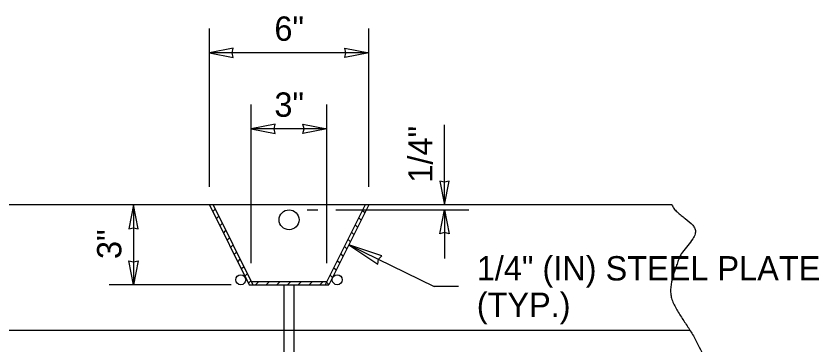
# Model space of a CAD drawing. Extents: x 99862 to 103151, y 100000 to 117076.
# Drawn here: x 101760 to 102289, y 109980 to 110196 of the extents above; entities that cross this region are included whole.
import ezdxf

# ---------------------------------------------------------------- set-up
doc = ezdxf.new("R2010")
doc.units = 0
for name, color, linetype in [('Level 10', 7, 'Continuous'), ('Level 11', 7, 'Continuous'), ('Level 14', 7, 'Continuous'), ('Level 15', 7, 'Continuous'), ('Level 16', 7, 'Continuous'), ('Level 20', 7, 'Continuous'), ('Level 30', 7, 'Continuous'), ('Level 40', 7, 'Continuous')]:
    doc.layers.add(name, color=color, linetype=linetype)

msp = doc.modelspace()

# ---------------------------------------------------------------- linework, layer by layer
at = {"layer": 'Level 10'}
for centre, radius in [((101939.66, 110062.11), 6.56), ((101907.82, 110022.67), 3.28), ((101971.4, 110022.67), 3.28)]:
    msp.add_circle(centre, radius, dxfattribs=at)
at = {"layer": 'Level 11'}
msp.add_line((102191.96, 110071.89), (101647.03, 110071.89), dxfattribs=at)
msp.add_spline([(102191.96, 110071.89), (102193.22, 110069.54), (102195.32, 110067.28), (102200.74, 110062.92), (102205.63, 110058.55), (102207.07, 110056.29), (102207.4, 110055.12), (102207.42, 110053.93), (102207.2, 110052.86), (102205.67, 110049.64), (102202.39, 110045.28), (102198.86, 110040.8), (102197.41, 110038.5), (102196.37, 110036.15), (102195.3, 110033.02), (102194.16, 110029.73), (102192.08, 110022.91), (102191.05, 110016.09), (102191.21, 110012.82), (102191.5, 110011.23), (102191.96, 110009.7), (102195.13, 110002.95), (102199.2, 109996.43), (102203.51, 109989.93), (102205.55, 109986.62), (102207.4, 109983.24), (102209.24, 109979.65), (102214.83, 109968.51), (102217.73, 109961.06), (102218.67, 109957.4), (102218.97, 109955.61), (102219.08, 109954.72), (102219.16, 109953.84), (102216.82, 109947.2), (102210.8, 109941.21), (102204, 109935.1), (102201.21, 109931.76), (102199.31, 109928.11), (102191.96, 109906.89)], degree=3, dxfattribs=at)
at = {"layer": 'Level 14'}
for p, q in [((101936.38, 109906.89), (101936.38, 110019.39)), ((101942.94, 109906.89), (101942.94, 110019.39))]:
    msp.add_line(p, q, dxfattribs=at)
at = {"layer": 'Level 15'}
for p, q in [((101887.16, 110083.89), (101887.16, 110187.89)), ((101992.16, 110083.89), (101992.16, 110187.89)), ((101992.16, 110171.89), (101887.16, 110171.89)), ((101914.76, 110033.58), (101914.76, 110137.89)), ((101964.56, 110033.58), (101964.56, 110137.89)), ((102042.16, 110071.89), (102042.16, 110124.55)), ((101964.56, 110121.89), (101914.76, 110121.89)), ((101837.16, 110071.89), (101837.16, 110019.39)), ((101951.66, 110068.68), (101958.56, 110068.68)), ((101970.56, 110068.68), (102058.16, 110068.68)), ((102042.16, 110068.68), (102042.16, 110036.68)), ((101979.04, 110045.64), (102035.33, 110018.19)), ((101901.41, 110019.39), (101821.16, 110019.39)), ((102051.33, 110018.19), (102035.33, 110018.19))]:
    msp.add_line(p, q, dxfattribs=at)
for points in [[(101887.16, 110171.89), (101902.89, 110168.81), (101902.16, 110171.89), (101902.89, 110174.97)], [(101992.16, 110171.89), (101976.44, 110168.81), (101977.17, 110171.89), (101976.44, 110174.97)], [(101914.76, 110121.89), (101930.49, 110118.81), (101929.76, 110121.89), (101930.49, 110124.97)], [(101964.56, 110121.89), (101948.84, 110118.81), (101949.56, 110121.89), (101948.84, 110124.97)], [(102042.16, 110071.89), (102045.25, 110087.62), (102042.16, 110086.89), (102039.08, 110087.62)], [(101837.16, 110071.89), (101834.08, 110056.17), (101837.16, 110056.89), (101840.25, 110056.17)], [(102042.16, 110068.68), (102045.25, 110052.95), (102042.16, 110053.68), (102039.08, 110052.95)], [(101979.04, 110045.64), (101998.25, 110032.95), (101998.61, 110036.1), (102000.87, 110038.32)], [(101837.16, 110019.39), (101834.08, 110035.12), (101837.16, 110034.39), (101840.25, 110035.12)]]:
    msp.add_lwpolyline(points, close=True, dxfattribs=at)
at = {"layer": 'Level 16'}
msp.add_line((101965.9, 110019.39), (101965.93, 110019.42), dxfattribs=at)
at = {"layer": 'Level 30'}
for p, q in [((101887.16, 110071.89), (101913.41, 110019.39)), ((101889.61, 110071.89), (101915.86, 110019.39)), ((101989.72, 110071.89), (101963.47, 110019.39)), ((101992.16, 110071.89), (101965.91, 110019.39)), ((101889.35, 110067.52), (101890.98, 110069.15)), ((101989.51, 110066.58), (101987.88, 110068.21)), ((101891.7, 110062.81), (101893.33, 110064.44)), ((101894.06, 110058.1), (101895.69, 110059.73)), ((101987.15, 110061.86), (101985.52, 110063.49)), ((101896.42, 110053.38), (101898.05, 110055.01)), ((101984.79, 110057.15), (101983.16, 110058.78)), ((101898.77, 110048.67), (101900.4, 110050.3)), ((101980.08, 110047.72), (101978.45, 110049.35)), ((101982.44, 110052.44), (101980.81, 110054.07)), ((101901.13, 110043.95), (101902.76, 110045.58)), ((101977.72, 110043.01), (101976.09, 110044.64)), ((101903.49, 110039.24), (101905.12, 110040.87)), ((101975.36, 110038.29), (101973.73, 110039.92)), ((101905.84, 110034.53), (101907.48, 110036.16)), ((101973.01, 110033.58), (101971.38, 110035.21)), ((101908.2, 110029.81), (101909.83, 110031.44)), ((101970.65, 110028.87), (101969.02, 110030.5)), ((101910.56, 110025.1), (101912.19, 110026.73)), ((101968.29, 110024.15), (101966.66, 110025.78)), ((101912.92, 110020.38), (101914.55, 110022.01)), ((101913.41, 110019.39), (101965.91, 110019.39)), ((101914.76, 110021.58), (101964.56, 110021.58)), ((101917.47, 110019.39), (101919.66, 110021.58)), ((101924.54, 110019.39), (101926.73, 110021.58)), ((101931.61, 110019.39), (101933.8, 110021.58)), ((101938.68, 110019.39), (101940.87, 110021.58)), ((101945.76, 110019.39), (101947.94, 110021.58)), ((101952.83, 110019.39), (101955.01, 110021.58)), ((101959.9, 110019.39), (101962.08, 110021.58)), ((101965.94, 110019.44), (101964.31, 110021.07))]:
    msp.add_line(p, q, dxfattribs=at)
at = {"layer": 'Level 40'}
msp.add_line((101637.45, 109989.39), (102203.86, 109989.39), dxfattribs=at)

# ---------------------------------------------------------------- texts
at = {"layer": 'Level 20'}
for s, p in [('6"', (101930, 110179.89)), ('3"', (101930, 110129.89))]:
    msp.add_text(s, height=16, dxfattribs=at).set_placement(p)
for s, rotation, p in [('1/4"', 90, (102034.16, 110086.54)), ('3"', 90, (101829.16, 110036.28)), ('1/4" (IN) STEEL PLATE', 360, (102063.33, 110022.19)), ('(TYP.)', 360, (102063.33, 109998.19))]:
    msp.add_text(s, height=16, rotation=rotation, dxfattribs=at).set_placement(p)

doc.saveas('drawing.dxf')
